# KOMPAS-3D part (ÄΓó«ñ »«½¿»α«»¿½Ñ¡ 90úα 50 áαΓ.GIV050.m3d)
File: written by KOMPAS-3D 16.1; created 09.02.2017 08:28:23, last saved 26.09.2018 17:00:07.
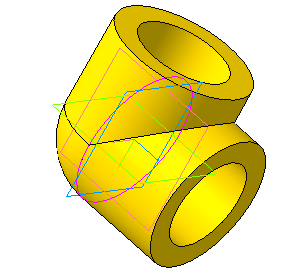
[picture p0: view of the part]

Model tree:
1. Эскиз:1
2. Операция выдавливания:9
     Расстояние 1 = 41.5
3. Массив по концентрической сетке:1  (with: Операция выдавливания:9, Эскиз:1)  (2 pattern instances)
     Геометрический массив = 1; Шаг 2 = 90
4. Эскиз:20
5. Вырезать элемент выдавливания:6
     Расстояние 1 = 41.5
6. Эскиз:21
7. Вырезать элемент выдавливания:7
     Расстояние 1 = 41.5
8. Эскиз:22
9. Вырезать элемент выдавливания:8
     Расстояние 1 = 20.5
10. Массив по концентрической сетке:3  (with: Вырезать элемент выдавливания:8, Эскиз:22)  (2 pattern instances)
     Геометрический массив = 1; Шаг 2 = 90
11. Эскиз:23
12. Операция вращения:1
     Угол 1 = 90; Угол 2 = 360

Expressions: 40-3.7*2
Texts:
  Отвод полипропилен 90гр 50 арт.GIV050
